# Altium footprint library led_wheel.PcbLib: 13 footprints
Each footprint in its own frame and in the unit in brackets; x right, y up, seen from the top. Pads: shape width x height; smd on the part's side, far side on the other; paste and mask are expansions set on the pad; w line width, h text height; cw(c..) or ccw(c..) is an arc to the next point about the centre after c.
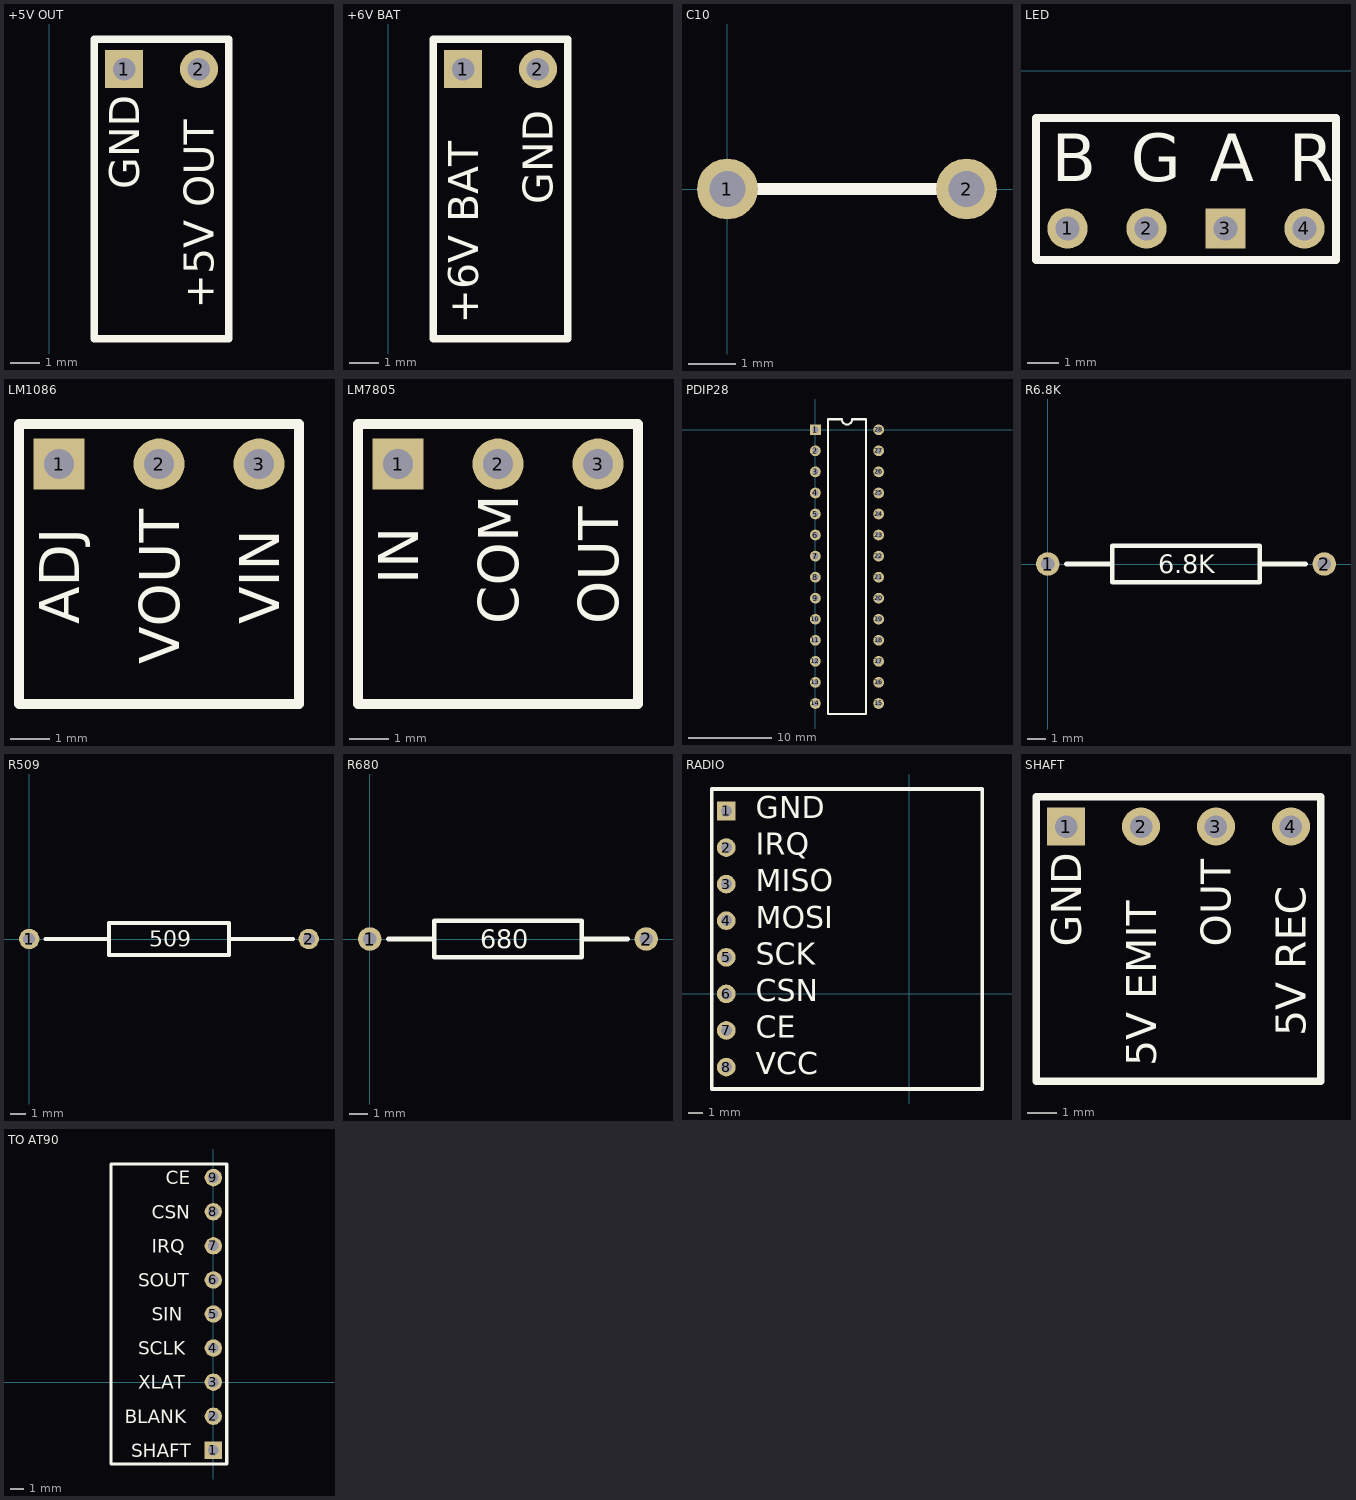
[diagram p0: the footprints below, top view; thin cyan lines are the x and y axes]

## +5V OUT [mil]
pads (2):
  rect 51x51 hole 30: 1(100,-100)
  round 51 hole 30: 2(200,-100)
Top Overlay:
  lines w10: 60,-460 240,-460 240,-60 60,-60 60,-460
  text "+5V OUT" at 220,-420 h40
  text "GND" at 120,-260 h40

## +6V BAT [mil]
pads (2):
  rect 51x51 hole 30: 1(100,-100)
  round 51 hole 30: 2(200,-100)
Top Overlay:
  lines w10: 60,-460 240,-460 240,-60 60,-60 60,-460
  text "+6V BAT" at 120,-440 h40
  text "GND" at 220,-280 h40

## C10 [mil]
pads (2):
  round 51 hole 30: 1(0,0) 2(200,0)
Top Overlay:
  lines w10: 0,0 200,0

## LED [mil]
pads (4):
  round 51 hole 30: 1(200,-200) 2(300,-200) 4(500,-200)
  rect 51x51 hole 30: 3(400,-200)
Top Overlay:
  lines w10: 160,-240 160,-60 540,-60 540,-240 160,-240
  text "R" at 480,-140 h60
  text "A" at 380,-140 h60
  text "G" at 280,-140 h60
  text "B" at 180,-140 h60

## LM1086 [mil]
pads (3):
  rect 51x51 hole 30: 1(100,-100)
  round 51 hole 30: 2(200,-100) 3(300,-100)
Top Overlay:
  lines w10: 60,-340 340,-340 340,-60 60,-60 60,-340
  text "VIN" at 320,-260 h40
  text "VOUT" at 220,-300 h40
  text "ADJ" at 120,-260 h40

## LM7805 [mil]
pads (3):
  rect 51x51 hole 30: 1(100,-100)
  round 51 hole 30: 2(200,-100) 3(300,-100)
Top Overlay:
  lines w10: 60,-340 340,-340 340,-60 60,-60 60,-340
  text "OUT" at 320,-260 h40
  text "COM" at 220,-260 h40
  text "IN" at 120,-220 h40

## PDIP28 [mil]
pads (28):
  rect 51x51 hole 30: 1(0,0)
  round 51 hole 30: 2(0,-100) 3(0,-200) 4(0,-300) 5(0,-400) 6(0,-500) 7(0,-600) 8(0,-700) 9(0,-800) 10(0,-900) 11(0,-1000) 12(0,-1100) 13(0,-1200) 14(0,-1300) 15(300,-1300) 16(300,-1200) 17(300,-1100) 18(300,-1000) 19(300,-900) 20(300,-800) 21(300,-700) 22(300,-600) 23(300,-500) 24(300,-400) 25(300,-300) 26(300,-200) 27(300,-100) 28(300,0)
Top Overlay:
  lines w10: 60.5,-1350 60.5,50 125,50 ccw(c150,50) 175,50 239.5,50 239.5,-1350 60.5,-1350

## R6.8K [mil]
pads (2):
  round 51 hole 30: 1(0,0) 2(600,0)
Top Overlay:
  lines w10: 40,0 140,0 ; 460,0 560,0 ; 140,-40 460,-40 460,40 140,40 140,-40
  text "6.8K" at 240,-20 h40

## R509 [mil]
pads (2):
  round 51 hole 30: 1(0,0) 2(700,0)
Top Overlay:
  lines w10: 41,0 200,0 ; 500,0 660,0 ; 200,-40 200,40 500,40 500,-40 200,-40
  text "509" at 300,-20 h40

## R680 [mil]
pads (2):
  round 51 hole 30: 1(0,0) 2(600,0)
Top Overlay:
  lines w10: 40,0 140,0 ; 460,0 560,0 ; 140,-40 460,-40 460,40 140,40 140,-40
  text "680" at 240,-20 h40

## RADIO [mil]
pads (8):
  rect 51x51 hole 30: 1(-500,500)
  round 51 hole 30: 2(-500,400) 3(-500,300) 4(-500,200) 5(-500,100) 6(-500,0) 7(-500,-100) 8(-500,-200)
Top Overlay:
  lines w10: -540,-260 -360,-260 200,-260 200,20 200,320 200,560 -200,560 -540,560 -540,60 -540,-260
  text "VCC" at -420,-220 h60
  text "CE" at -420,-120 h60
  text "CSN" at -420,-20 h60
  text "SCK" at -420,80 h60
  text "MOSI" at -420,180 h60
  text "MISO" at -420,280 h60
  text "IRQ" at -420,380 h60
  text "GND" at -420,480 h60

## SHAFT [mil]
pads (4):
  rect 51x51 hole 30: 1(100,-100)
  round 51 hole 30: 2(200,-100) 3(300,-100) 4(400,-100)
Top Overlay:
  lines w10: 60,-440 60,-60 440,-60 440,-440 60,-440
  text "GND" at 120,-260 h40
  text "5V EMIT" at 220,-420 h40
  text "OUT" at 320,-260 h40
  text "5V REC" at 420,-380 h40

## TO AT90 [mil]
pads (9):
  rect 51x51 hole 30: 1(0,-200)
  round 51 hole 30: 2(0,-100) 3(0,0) 4(0,100) 5(0,200) 6(0,300) 7(0,400) 8(0,500) 9(0,600)
Top Overlay:
  lines w10: -300,-240 -300,240 -300,640 -120,640 40,640 40,240 40,-240 -300,-240
  text "CE" at -140,580 h40
  text "SHAFT" at -240,-220 h40
  text "SIN" at -180,180 h40
  text "SCLK" at -220,80 h40
  text "XLAT" at -220,-20 h40
  text "BLANK" at -260,-120 h40
  text "SOUT" at -220,280 h40
  text "IRQ" at -180,380 h40
  text "CSN" at -180,480 h40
